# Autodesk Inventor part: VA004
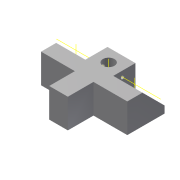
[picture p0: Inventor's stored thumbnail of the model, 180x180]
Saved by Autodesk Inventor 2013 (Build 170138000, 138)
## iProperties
Manager: P MOLOY
Company: NUIG
Shininess: 64.0
Length Units: 11269
Angle Units: 11279
Time Units: 11290
Mass Units: 11283
Length Display Precision: 3
Angle Display Precision: 2
Compacted: True
Part Number: VA004
Document SubType Name: Modeling
Created: 2004-12
Designer: warren davies
Manufacturer: Standard
Standards Organization: Custom
Project: TRAINING VICE ASSY
Material: Steel, Mild
Mass: 445.859 g
Surface Area: 124.128 cm^2
Volume: 56.725 cm^3
Density: 7.86 g/cm^3
Density: 0.0
Volumn: 0.0
Area: 0.0
PropertySet Name: Model Information
Control State: 0
Master: False
Checked Out: False
Title: MOVABLE JAW
Subject: VICE ASSEMBLY
Author: warren davies
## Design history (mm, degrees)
sketch "Sketch1"
  geometry: L1 (-11.643, -16.119)-(4.357, -16.119); L2 (4.357, -16.119)-(4.357, 5.881); L3 (-11.643, -16.119)-(-11.643, 5.881); L4 (-11.643, 5.881)-(-40.643, 5.881); L5 (-40.643, 5.881)-(-40.643, 37.881); L6 (-3.643, -16.119)-(-3.643, 48.286); L7 (33.357, 5.881)-(33.357, 37.881); L8 (4.357, 5.881)-(33.357, 5.881); L9 (-40.643, 37.881)-(33.357, 37.881)
  constraints: 18 end point, 4 parallel, 3 perpendicular, 2 symmetric about line, 1 horizontal, 1 midpoint, 2 other
  dimensions: "d0" = 16 distance of L1.start L1.end; "d1" = 22 distance of L1.end L2.end; "d2" = 29 distance of L3.end L4.end; "d3" = 32 distance of L4.end L5.end
extrude "Extrusion1" new body sketch "Sketch1" distance "d5" = 25; taper "d6" = 0 deg
sketch "Sketch2"
  geometry: L1 (25, 0)-(25, 32) reference; L2 (0, 32)-(25, 32) reference; L3 (6, 32)-(25, 13)
  constraints: 2 end point, 2 point on line
  dimensions: "d7" = 13 distance of L1.start L3.end; "d8" = 45 deg angle of L3 L1
extrude "Extrusion2" cut sketch "Sketch2" stored distance "d9" = 25; taper "d10" = 0 deg
sketch "Sketch3"
  geometry: L1 (33.357, 18.881)-(-40.643, 18.881) reference; L2 (-40.643, 37.881)-(33.357, 37.881) reference; L3 (-15.643, 18.881)-(8.357, 18.881); L4 (8.357, 18.881)-(8.357, 37.881); L5 (8.357, 37.881)-(-15.643, 37.881); L6 (-15.643, 37.881)-(-15.643, 18.881); L7 (-40.643, 18.881)-(-40.643, 37.881) reference
  constraints: 8 end point, 2 parallel, 2 point on line, 1 horizontal, 1 perpendicular
  dimensions: "d11" = 24 distance between parallel lines of L4 L6; "d12" = 25 distance between parallel lines of L7 L6
extrude "Extrusion3" join sketch "Sketch3" stored distance "d13" = 25; taper "d14" = 0 deg
sketch "Sketch4"
  geometry: L1 (-11.643, 5.881)-(-40.643, 5.881) reference; L2 (8.357, 18.881)-(8.357, 37.881) reference; C1 r 5 at (-3.643, 26.881)
  constraints: 1 centre point
  dimensions: "d15" = 10 diameter of C1; "d17" = 21 distance from line of C1.centre L1; "d46" = 12 distance from line of L2 C1.centre
extrude "Extrusion4" cut sketch "Sketch4" distance "d18" = 13; taper "d19" = 0 deg
sketch "Sketch5"
  geometry: L1 (-40.643, 37.881)-(-15.643, 37.881) reference; L2 (-40.643, 18.881)-(-40.643, 37.881) reference; L3 (33.357, 37.881)-(33.357, 18.881) reference; C1 r 3 at (-28.643, 23.881); C2 r 3 at (21.357, 23.881)
  constraints: 2 centre point, 1 equal radius, 1 horizontal alignment
  dimensions: "d22" = 14 distance from line of L1 C1.centre; "d23" = 12 distance from line of L2 C1.centre; "d24" = 6 diameter of C1; "d25" = 12 distance from line of L3 C2.centre
extrude "Extrusion5" cut sketch "Sketch5" stored distance "d26" = 13; taper "d27" = 0 deg
sketch "Sketch9"
  geometry: L1 (0, 19)-(0, 0) reference; L2 (0, 19)-(-19, 19) reference; L3 (0, 0)-(-19, 19) reference; C1 r 1.5 at (-5, 8)
  constraints: 1 centre point
  dimensions: "d37" = 5 distance from line of L1 C1.centre; "d38" = 11 distance from line of C1.centre L2; "d39" = 3 diameter of C1
extrude "Extrusion8" cut sketch "Sketch9" stored distance "d40" = 20; taper "d41" = 0 deg
workaxis "Work Axis1"
workaxis "Work Axis2"
workaxis "Work Axis3"
workaxis "Work Axis4"
thread "Thread4" dims "d47" = 10, "d48" = 0
thread "Thread5" dims "d49" = 10, "d50" = 0
body "Solid1"
